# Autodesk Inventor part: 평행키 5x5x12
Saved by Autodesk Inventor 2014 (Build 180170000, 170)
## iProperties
Created: 2024-08
Part Number: 평행키 5x5x12
Material: 일반
Document SubType Name: Modeling
Designer: dg
Density: 1 g/cm^3
Appearance: 기본값
Author: dg
Author: jhkim
Description: 키 및 해당 키홈
Creation Date: 2024-08-09
Sending System: Autodesk Inventor 2025
Preprocessor: ST-DEVELOPER v20
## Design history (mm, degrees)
node "평행키 5x5x121"
body "Solid1"
node "기준1"
